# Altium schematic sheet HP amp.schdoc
size 205 x 64 mm
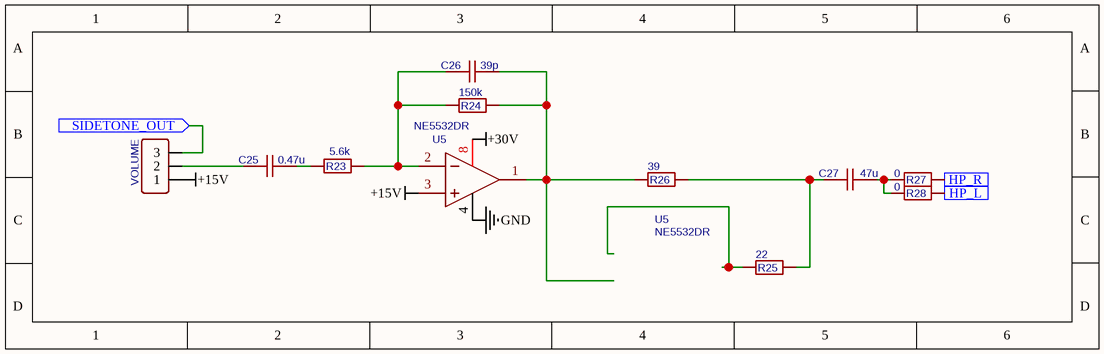
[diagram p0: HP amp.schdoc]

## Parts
(Parts that share a designator on the sheet are numbered #1, #2 ... from top to bottom, then left to right.)
C25  0.47u  [C0805]
C26  39p  [C0805]
C27  47u  [C0805]
J2  VOLUME  [HDR-M-2.54_1X3]
R23  5.6k  [R0805]
R24  150k  [R0805]
R25  22  [R1206]
R26  39  [R0805]
R27  0  [R1206]
R28  0  [R1206]
U5#1  NE5532DR  [SOIC-8_L4.9-W3.9-P1.27-LS6.0-BL]
U5#2  NE5532DR  [SOIC-8_L4.9-W3.9-P1.27-LS6.0-BL]

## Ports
HP_L (in), HP_R (in), SIDETONE_OUT (in)

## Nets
+15V: J2.1 U5#1.3(IN1+)
+30V: U5#1.8(VCC+)
GND: U5#1.4(VCC-/GND)
HP_L: R28.2 ; port HP_L
HP_R: R27.2 ; port HP_R
SIDETONE_OUT: J2.3 ; port SIDETONE_OUT
NetC25_1: C25.1 J2.2
NetC25_2: C25.2 R23.1
NetC26_1: C26.1 R23.2 R24.1 U5#1.2(IN1-)
NetC26_2: C26.2 R24.2 R26.1 U5#1.1(OUT1)
NetC27_1: C27.1 R25.2 R26.2
NetC27_2: C27.2 R27.1 R28.1

Not connected (* = marked no-connect by the designer): R25 1

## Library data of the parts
C25 = 0.47u: BOM_Manufacturer Part: CL21B474KBFNNNE; BOM_Manufacturer: SAMSUNG(三星); nameAlias: Value(F); Contributor: LCEDA_Lib
C26 = 39p: BOM_Manufacturer Part: CL21C470JBANNNC; BOM_Manufacturer: SAMSUNG(三星); nameAlias: Value(F); Contributor: LCEDA_Lib
C27 = 47u: BOM_Manufacturer Part: CL21A476MQYNNNE; BOM_Manufacturer: SAMSUNG(三星); nameAlias: Value(F); Contributor: LCEDA_Lib
J2 = VOLUME: Contributor: LCEDA_Lib
R23 = 5.6k: BOM_Manufacturer Part: 0805W8F5601T5E; BOM_Manufacturer: UNI-ROYAL(厚声); nameAlias: Value(Ω); Contributor: LCEDA_Lib
R24 = 150k: BOM_Manufacturer Part: 0805W8F1503T5E; BOM_Manufacturer: UNI-ROYAL(厚声); nameAlias: Value(Ω); Contributor: LCEDA_Lib
R25 = 22: BOM_Manufacturer Part: 1206W4F220JT5E; BOM_Manufacturer: UNI-ROYAL(厚声); nameAlias: Value(Ω); Contributor: LCEDA_Lib
R26 = 39: BOM_Manufacturer Part: 0805W8F330JT5E; BOM_Manufacturer: UNI-ROYAL(厚声); nameAlias: Value(Ω); Contributor: LCEDA_Lib
R27 R28 = 0: nameAlias: Value(Ω); Contributor: LCEDA_Lib
U5#1 U5#2 = NE5532DR: BOM_Manufacturer: TI(德州仪器); subpart_no: 2; SMT Type: Basic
